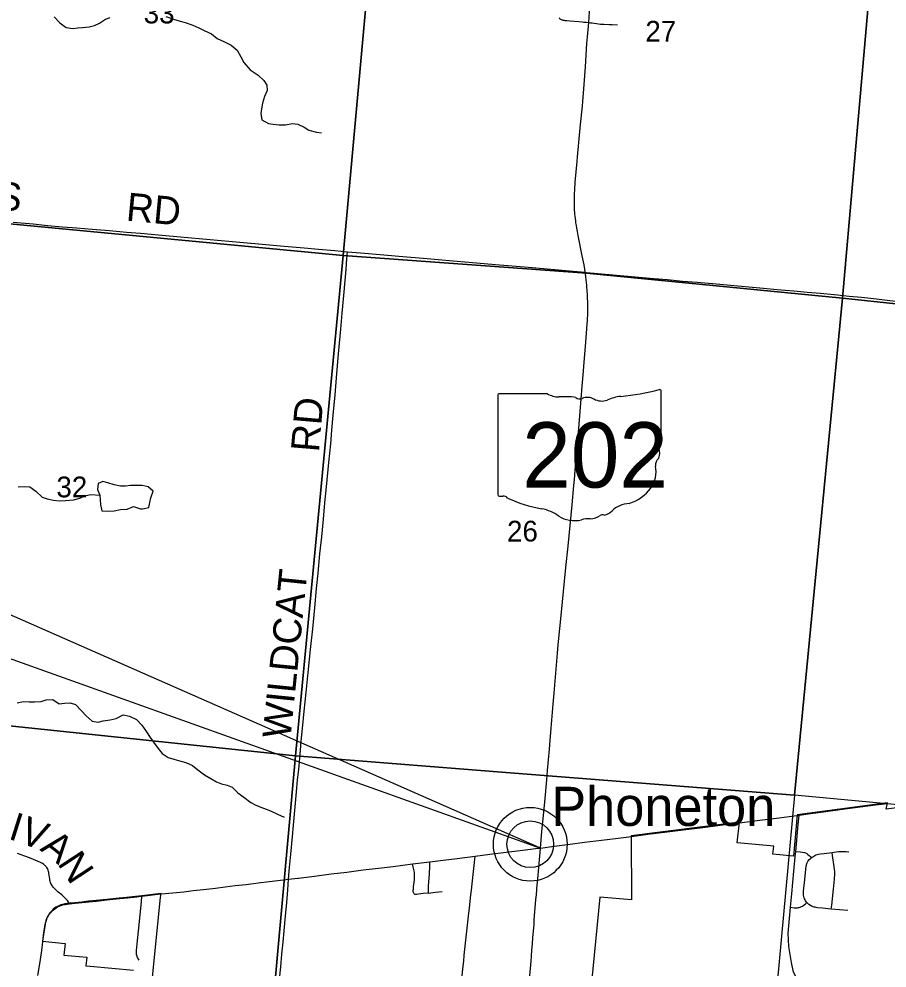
# Model space of a CAD drawing. Extents: x -38.1 to 35.9, y -2.7 to 28.5.
# Drawn here: x 10.521 to 12.272, y 15.8 to 17.716 of the extents above; entities that cross this region are included whole.
import ezdxf

# ---------------------------------------------------------------- set-up
doc = ezdxf.new("R2010")
doc.units = 0
for name, color, linetype in [('GM_X_City_Street', 7, 'Continuous'), ('GM_X_City_Street_Text', 7, 'Continuous'), ('GM_X_County_Road_Text', 7, 'Continuous'), ('GM_X_County_ROW', 7, 'Continuous'), ('GM_X_Interchange_Ramps', 7, 'Continuous'), ('GM_X_Major_River', 7, 'Continuous'), ('GM_X_Major_River_Text', 7, 'Continuous'), ('GM_X_Minor_Lake', 7, 'Continuous'), ('GM_X_Minor_River', 7, 'Continuous'), ('GM_X_Section', 7, 'Continuous'), ('GM_X_Section_Text', 7, 'Continuous'), ('GM_X_State_Location', 7, 'Continuous'), ('GM_X_Township', 7, 'Continuous'), ('GM_X_Township_Subdivision_Text', 7, 'Continuous'), ('GM_X_US_Route', 7, 'Continuous'), ('SC_Scratch10', 7, 'Continuous'), ('SH_Data', 7, 'Continuous')]:
    doc.layers.add(name, color=color, linetype=linetype)

msp = doc.modelspace()

# ---------------------------------------------------------------- linework, layer by layer
at = {"layer": 'GM_X_City_Street'}
for points in [[(12.1292, 15.6704), (12.132, 15.7051), (12.1322, 15.7158), (12.1298, 15.7265), (12.1267, 15.7376), (12.1232, 15.7458), (12.1172, 15.7524), (12.109, 15.7602), (12.0989, 15.7688), (12.0901, 15.7785), (12.0837, 15.7912), (12.0794, 15.8105), (12.0743, 15.8428), (12.0726, 15.8703), (12.0757, 15.8994), (12.0778, 15.9222), (12.0802, 15.9495), (12.0846, 15.9951), (12.0873, 16.0243), (12.0883, 16.0352), (12.0931, 16.0896), (12.0949, 16.1084)], [(12.0883, 16.0352), (12.0974, 16.0344), (12.1021, 16.0338), (12.1057, 16.033), (12.1081, 16.0321), (12.1104, 16.0308), (12.1129, 16.029), (12.1153, 16.027), (12.1173, 16.0249), (12.1195, 16.0221), (12.1224, 16.0243), (12.1248, 16.0258), (12.1269, 16.027), (12.129, 16.028), (12.1313, 16.0287), (12.1339, 16.0293), (12.1379, 16.0301), (12.1453, 16.0311), (12.1619, 16.0331), (12.1748, 16.0346), (12.1802, 16.0351), (12.1848, 16.0352), (12.1901, 16.0349), (12.1951, 16.0344)], [(12.1934, 15.9158), (12.1599, 15.9188), (12.1425, 15.9203), (12.1321, 15.9215), (12.1296, 15.9218), (12.1272, 15.9223), (12.1254, 15.9227), (12.1236, 15.9233), (12.1216, 15.924), (12.1193, 15.925), (12.1177, 15.9259), (12.1147, 15.928), (12.1126, 15.9298), (12.1108, 15.9318), (12.1094, 15.9336), (12.1082, 15.9356), (12.1071, 15.9376), (12.1062, 15.9395), (12.1054, 15.9415), (12.1047, 15.9439), (12.1042, 15.9466), (12.1041, 15.9494), (12.104, 15.9518), (12.1041, 15.9546), (12.1066, 15.9782), (12.108, 15.9926), (12.1092, 16.0052), (12.1097, 16.0076), (12.1106, 16.011), (12.1118, 16.0137), (12.1133, 16.0159), (12.1149, 16.0179), (12.1172, 16.0202), (12.1195, 16.0221)], [(12.1599, 15.9188), (12.1608, 15.9268), (12.1642, 15.9588), (12.1662, 15.9791), (12.1669, 15.9897), (12.167, 15.9928), (12.1669, 15.9953), (12.1667, 15.998), (12.166, 16.0037), (12.1627, 16.0271), (12.1619, 16.0331)], [(10.763, 15.8153), (10.7598, 15.8207), (10.7589, 15.8228), (10.7583, 15.8248), (10.7579, 15.8271), (10.7577, 15.8312), (10.7578, 15.8351), (10.759, 15.8488), (10.7617, 15.8742), (10.765, 15.907), (10.7678, 15.9331), (10.7687, 15.9447)], [(12.0778, 15.9222), (12.0848, 15.9215), (12.0886, 15.9213), (12.0919, 15.9214), (12.0935, 15.9216), (12.0951, 15.9219), (12.0968, 15.9223), (12.0984, 15.9229), (12.1, 15.9236), (12.1016, 15.9246), (12.105, 15.927), (12.1078, 15.9292), (12.1108, 15.9318)]]:
    msp.add_lwpolyline(points, dxfattribs=at)
at = {"layer": 'GM_X_City_Street_Text'}
for points in [[(10.5085, 17.3054), (10.5492, 17.3018), (10.5782, 17.2989), (10.6083, 17.2963), (10.6375, 17.2938), (10.6684, 17.2914), (10.7035, 17.2884), (10.7375, 17.2854), (10.766, 17.283), (10.809, 17.2792), (10.8464, 17.2758), (10.9665, 17.2651), (11.0184, 17.2603), (11.0558, 17.257), (11.0962, 17.2536), (11.125, 17.2509), (11.1577, 17.2481), (11.1835, 17.2458)], [(11.1835, 17.2458), (11.2097, 17.2436), (11.2496, 17.2401), (11.287, 17.2368), (11.3445, 17.2318), (11.3668, 17.2299), (11.3965, 17.2275), (11.4281, 17.2249), (11.482, 17.2201), (11.5073, 17.2179), (11.5408, 17.215), (11.6095, 17.2089), (11.6392, 17.2062), (11.6635, 17.2042)], [(11.6635, 17.2042), (11.6658, 17.204), (11.719, 17.1992), (11.7718, 17.1946), (11.8019, 17.1918), (11.8297, 17.1894), (11.8594, 17.1866), (11.8891, 17.184), (11.9275, 17.1807), (11.9789, 17.1762), (12.0228, 17.1722), (12.0507, 17.1697), (12.0841, 17.1667), (12.1113, 17.1642), (12.1379, 17.1618), (12.1725, 17.1585), (12.196, 17.1562), (12.2207, 17.1537), (12.251, 17.1504), (12.2778, 17.1474), (12.3036, 17.1446), (12.3242, 17.1423)], [(10.6222, 15.9293), (10.6211, 15.9314), (10.6198, 15.9337), (10.6181, 15.9361), (10.616, 15.9385), (10.6144, 15.9402), (10.6109, 15.9434), (10.6068, 15.9472), (10.5997, 15.9531), (10.5921, 15.9602), (10.5896, 15.963), (10.5884, 15.9646), (10.5872, 15.9663), (10.5859, 15.9683), (10.585, 15.9705), (10.5842, 15.9725), (10.5835, 15.9748), (10.5829, 15.9771), (10.5825, 15.9794), (10.5808, 15.9904), (10.5805, 15.9927), (10.58, 15.9948), (10.5794, 15.9971), (10.5787, 15.999), (10.5778, 16.0008), (10.5768, 16.0024), (10.5759, 16.0036), (10.5748, 16.0049), (10.574, 16.0058), (10.5729, 16.0067), (10.5716, 16.0079), (10.5699, 16.0091), (10.5679, 16.0104), (10.5656, 16.0117), (10.5628, 16.0131), (10.5594, 16.0148), (10.5501, 16.0186), (10.5415, 16.0221), (10.5322, 16.0256), (10.5177, 16.031)]]:
    msp.add_lwpolyline(points, dxfattribs=at)
at = {"layer": 'GM_X_County_ROW'}
msp.add_line((11.5524, 16.0495), (11.5524, 16.0495), dxfattribs=at)
at = {"layer": 'GM_X_Interchange_Ramps'}
for points in [[(11.5856, 16.1795), (11.5872, 16.1983), (11.5912, 16.2416), (11.5925, 16.259), (11.5945, 16.2837), (11.5989, 16.3326), (11.6006, 16.3543), (11.6075, 16.4353), (11.6089, 16.452), (11.6154, 16.5181), (11.6218, 16.5806), (11.6245, 16.6084), (11.6289, 16.651), (11.6371, 16.7345), (11.6406, 16.7735), (11.6416, 16.786), (11.6445, 16.8225), (11.649, 16.8748), (11.6502, 16.8888), (11.6573, 16.9741), (11.66, 17.0045), (11.6608, 17.015), (11.6639, 17.0546), (11.6674, 17.0992), (11.6678, 17.1067), (11.6684, 17.122), (11.6686, 17.1282), (11.6686, 17.1344), (11.6686, 17.1395), (11.668, 17.1572), (11.6674, 17.1682), (11.6669, 17.1737), (11.6665, 17.1792), (11.6662, 17.1828), (11.6654, 17.1899), (11.6648, 17.195), (11.664, 17.2012), (11.6635, 17.2042), (11.6626, 17.2102), (11.661, 17.2195), (11.6573, 17.2377), (11.6493, 17.2782), (11.6478, 17.2863), (11.6465, 17.2935), (11.6456, 17.2986), (11.6447, 17.3042), (11.6442, 17.3077), (11.6435, 17.3135), (11.6426, 17.3213), (11.642, 17.3328), (11.6415, 17.3466), (11.6415, 17.3531), (11.6418, 17.3626), (11.6422, 17.3707), (11.6432, 17.3864), (11.6468, 17.4278), (11.6477, 17.4376), (11.654, 17.5023), (11.6576, 17.5394), (11.6584, 17.5491), (11.6612, 17.5832), (11.6638, 17.6191), (11.6669, 17.6664), (11.6679, 17.6794), (11.6704, 17.7083), (11.6727, 17.7407)], [(11.5733, 16.0419), (11.576, 16.0752), (11.579, 16.1073), (11.5823, 16.142), (11.5856, 16.1795)], [(11.5658, 15.9605), (11.5674, 15.9799), (11.5697, 16.0028), (11.5732, 16.0411), (11.5733, 16.0419)], [(11.5379, 15.6318), (11.5386, 15.6393), (11.5413, 15.6702), (11.5426, 15.6831), (11.5462, 15.7227), (11.5501, 15.7685), (11.5503, 15.772), (11.5513, 15.7846), (11.554, 15.8136), (11.5557, 15.8353), (11.5567, 15.8489), (11.5577, 15.8606), (11.56, 15.8885), (11.5606, 15.8976), (11.5618, 15.9131), (11.5639, 15.9378), (11.5647, 15.9471), (11.5656, 15.9576), (11.5658, 15.9605)]]:
    msp.add_lwpolyline(points, dxfattribs=at)
at = {"layer": 'GM_X_Major_River'}
for points in [[(12.0949, 16.1084), (12.1179, 16.1115), (12.1444, 16.115), (12.1826, 16.1202), (12.2179, 16.1248), (12.2491, 16.1289), (12.2735, 16.132)], [(11.9748, 16.0928), (12.0159, 16.098), (12.0545, 16.1031), (12.0949, 16.1084)], [(11.7565, 16.0655), (11.7895, 16.0697), (11.8284, 16.0746), (11.8613, 16.0787), (11.9007, 16.0836), (11.9412, 16.0889), (11.9748, 16.0928)], [(11.0845, 15.9813), (11.1168, 15.9853), (11.1503, 15.9896), (11.1825, 15.9935), (11.2153, 15.9976), (11.2464, 16.0015), (11.2754, 16.0048), (11.3149, 16.0097), (11.3498, 16.0141), (11.3765, 16.0174), (11.405, 16.021), (11.4409, 16.0253), (11.4709, 16.0295), (11.5036, 16.0336), (11.5374, 16.0375), (11.5685, 16.0413), (11.5733, 16.0419), (11.6009, 16.0456), (11.633, 16.0497), (11.662, 16.0535), (11.6965, 16.0579), (11.7296, 16.0621), (11.7565, 16.0655)], [(11.0546, 15.9778), (11.0646, 15.9791), (11.0836, 15.9812), (11.0845, 15.9813)], [(10.8078, 15.9492), (10.8311, 15.9515), (10.8531, 15.9538), (10.8721, 15.9559), (10.8932, 15.9582), (10.9172, 15.961), (10.9369, 15.9635), (10.9567, 15.966), (10.9788, 15.9685), (11.0029, 15.9715), (11.0257, 15.9743), (11.0546, 15.9778)], [(10.5686, 15.8528), (10.5702, 15.866), (10.5723, 15.8793), (10.5736, 15.8867), (10.5743, 15.8906), (10.5753, 15.8943), (10.5765, 15.898), (10.5777, 15.9011), (10.5791, 15.9039), (10.5809, 15.907), (10.5829, 15.9098), (10.5852, 15.9124), (10.5876, 15.915), (10.59, 15.9173), (10.5927, 15.9194), (10.5955, 15.9213), (10.5985, 15.9229), (10.6016, 15.9245), (10.6051, 15.9258), (10.609, 15.927), (10.6137, 15.928), (10.6178, 15.9287), (10.6222, 15.9293), (10.6339, 15.9305), (10.6477, 15.9318), (10.6612, 15.9332), (10.677, 15.9348), (10.698, 15.9371), (10.7233, 15.9398), (10.7393, 15.9416), (10.7585, 15.9437), (10.7687, 15.9447), (10.7799, 15.9459), (10.7951, 15.9478), (10.8078, 15.9492)], [(10.5586, 15.7845), (10.561, 15.7999), (10.5637, 15.8172), (10.5663, 15.8352), (10.5686, 15.8528)]]:
    msp.add_lwpolyline(points, dxfattribs=at)
at = {"layer": 'GM_X_Major_River_Text'}
for points in [[(11.6109, 17.7178), (11.6113, 17.7172), (11.6117, 17.7167), (11.6123, 17.7161), (11.6133, 17.7154), (11.6146, 17.7147), (11.6159, 17.7141), (11.6175, 17.7136), (11.6187, 17.7133), (11.621, 17.7129), (11.622, 17.7127), (11.6243, 17.7125), (11.6263, 17.7122), (11.6322, 17.7117), (11.6503, 17.7102), (11.6569, 17.7097), (11.6606, 17.7094), (11.6653, 17.7089), (11.6704, 17.7083)], [(11.6704, 17.7083), (11.6737, 17.708), (11.6774, 17.7075), (11.6902, 17.7057), (11.6943, 17.7053), (11.7006, 17.7048), (11.7115, 17.7044), (11.718, 17.7043), (11.7288, 17.7041)], [(11.0646, 15.9791), (11.0664, 16.0023), (11.0692, 16.0295), (11.0723, 16.0654), (11.0744, 16.0883), (11.0778, 16.1253), (11.0806, 16.1556), (11.0829, 16.1796), (11.085, 16.2007), (11.0884, 16.2396), (11.0902, 16.2575), (11.0925, 16.2829), (11.0962, 16.318), (11.1001, 16.3557), (11.1043, 16.3965), (11.1091, 16.4429), (11.1133, 16.4843), (11.1175, 16.5269), (11.1213, 16.5658), (11.1243, 16.5968), (11.1279, 16.6356), (11.1315, 16.6703), (11.1353, 16.7061), (11.1381, 16.739), (11.1411, 16.7708), (11.1461, 16.8203), (11.1496, 16.8581), (11.1521, 16.8853), (11.1547, 16.9156), (11.1584, 16.9571), (11.1615, 16.9911), (11.165, 17.0325), (11.1674, 17.0613), (11.1698, 17.0891), (11.1728, 17.1219), (11.1761, 17.1576), (11.179, 17.1874), (11.181, 17.2099), (11.1825, 17.2322), (11.1835, 17.2458)], [(11.4149, 15.784), (11.4163, 15.7978), (11.418, 15.8137), (11.4192, 15.8256), (11.4205, 15.8375), (11.4279, 15.9044), (11.4297, 15.9211), (11.4326, 15.9477), (11.4335, 15.9569), (11.4349, 15.9699), (11.4409, 16.0253)], [(11.3471, 15.9511), (11.3363, 15.9498), (11.3268, 15.9487), (11.3233, 15.9483), (11.3222, 15.9482), (11.3214, 15.9483), (11.3207, 15.9483), (11.32, 15.9484), (11.3188, 15.9489), (11.3178, 15.9496), (11.3171, 15.9506), (11.3166, 15.9518), (11.3165, 15.9526), (11.3164, 15.9537), (11.3164, 15.9551), (11.3164, 15.9568), (11.3166, 15.9587), (11.317, 15.9634), (11.3176, 15.9685), (11.3186, 15.9774), (11.3189, 15.9824), (11.319, 15.9868), (11.3185, 15.9918), (11.3178, 15.9959), (11.3162, 16.0038), (11.3149, 16.0097)], [(11.3471, 15.9511), (11.347, 15.9582), (11.3473, 15.966), (11.3477, 15.9727), (11.349, 15.9896), (11.3497, 16.0053), (11.3498, 16.0141)], [(11.0419, 15.7237), (11.0446, 15.7524), (11.0465, 15.7775), (11.0487, 15.8019), (11.0513, 15.8274), (11.0525, 15.8398), (11.0534, 15.8516), (11.0556, 15.8746), (11.0587, 15.9053), (11.0603, 15.9246), (11.0617, 15.9402), (11.0632, 15.9573), (11.0646, 15.9791)], [(11.3471, 15.9511), (11.3614, 15.9527), (11.3744, 15.9542)]]:
    msp.add_lwpolyline(points, dxfattribs=at)
at = {"layer": 'GM_X_Section'}
for points in [[(10.5918, 17.7197), (10.6027, 17.7078), (10.6154, 17.6985), (10.6294, 17.6961), (10.6393, 17.6975), (10.6488, 17.6985), (10.6621, 17.6999), (10.6731, 17.7024), (10.6827, 17.7072), (10.6949, 17.7154), (10.7044, 17.7183)], [(10.8171, 17.7204), (10.8325, 17.7153), (10.8458, 17.7113), (10.856, 17.7085), (10.8715, 17.7034), (10.8835, 17.698), (10.8941, 17.6921), (10.9088, 17.6855), (10.9208, 17.6759), (10.9351, 17.6692), (10.9487, 17.663), (10.9611, 17.6526), (10.9685, 17.6392), (10.9745, 17.6274), (10.9872, 17.6132), (11.003, 17.602), (11.0146, 17.5916), (11.0209, 17.5817), (11.0216, 17.5714), (11.0161, 17.5593), (11.0122, 17.5457), (11.0098, 17.5343), (11.0089, 17.5249), (11.0106, 17.5123), (11.0238, 17.5049), (11.0336, 17.5029), (11.0454, 17.502), (11.0587, 17.5022), (11.0723, 17.5044), (11.083, 17.5035), (11.0958, 17.4972), (11.1056, 17.4914), (11.1211, 17.4871), (11.1313, 17.4858)], [(10.5191, 16.7713), (10.5316, 16.7719), (10.5426, 16.771), (10.5546, 16.7625), (10.5674, 16.7502), (10.5772, 16.7467), (10.5905, 16.7442), (10.6018, 16.743), (10.6147, 16.7436), (10.6303, 16.7449), (10.6432, 16.7482), (10.6535, 16.7526), (10.6653, 16.7555), (10.6835, 16.7541)], [(10.517, 16.3349), (10.5299, 16.3378), (10.5409, 16.3369), (10.5515, 16.3368), (10.5656, 16.3377), (10.5755, 16.341), (10.5887, 16.342), (10.6019, 16.3328), (10.6125, 16.3345), (10.6235, 16.3352), (10.6349, 16.3316), (10.6469, 16.3186), (10.6562, 16.309), (10.6682, 16.2978), (10.6803, 16.2962), (10.6906, 16.2987), (10.7043, 16.3008), (10.7165, 16.3037), (10.731, 16.3107), (10.7438, 16.3079), (10.7574, 16.3013), (10.7686, 16.2898), (10.778, 16.2764), (10.7854, 16.2653), (10.7917, 16.2554), (10.8011, 16.2427), (10.8093, 16.2328), (10.8213, 16.2247), (10.8327, 16.2215), (10.847, 16.2175), (10.8572, 16.2144), (10.8704, 16.2085), (10.8813, 16.2), (10.8952, 16.1896), (10.9077, 16.1823), (10.919, 16.1753), (10.9292, 16.1714), (10.9405, 16.1686), (10.9507, 16.1647), (10.9619, 16.1535), (10.9744, 16.1443), (10.9886, 16.1339), (10.9984, 16.1284), (11.0139, 16.1222), (11.0283, 16.1171), (11.0422, 16.1105), (11.0554, 16.1039)]]:
    msp.add_lwpolyline(points, dxfattribs=at)
at = {"layer": 'GM_X_Section_Text'}
for p, q in [((11.5869, 16.9591), (11.4904, 16.9591)), ((11.8167, 16.8593), (11.8167, 16.964)), ((11.4871, 16.9556), (11.4871, 16.7555)), ((11.8167, 16.8594), (11.8167, 16.8593))]:
    msp.add_line(p, q, dxfattribs=at)
for centre, major_axis, start_param, end_param in [((11.4909, 16.956), (0.00382, 0), 1.712693, 3.28349), ((11.6099, 16.9823), (0.037, 0), 4.042523, 4.731795), ((11.6993, 17.2319), (0.3495, 0), 4.814394, 5.042369), ((11.8131, 16.9644), (0.00367, 0), 6.141152, 7.989035), ((11.6222, 16.8467), (0.133, 0), 1.404758, 1.657858), ((11.6524, 16.9571), (0.0107, 0), 3.836095, 5.185415), ((11.668, 16.9339), (0.0222, 0), 0.950623, 2.079405), ((11.6967, 16.9657), (0.0267, 0), 4.081561, 5.145723), ((11.7439, 16.8979), (0.0703, 0), 1.699011, 2.107814), ((11.8159, 16.8516), (0.00568, 0), 1.883978, 3.671073), ((11.7798, 16.8384), (0.0341, 0), 5.934695, 6.695948), ((11.8128, 16.8589), (0.00393, 0), 5.05454, 6.418171), ((11.8299, 16.8155), (0.0248, 0), 2.387724, 3.262537), ((11.7189, 16.8022), (0.0874, 0), 5.101752, 6.440018), ((11.4909, 16.755), (0.00385, 0), 3.00124, 4.508301), ((11.4915, 16.7755), (0.0294, 0), 4.665946, 4.897461), ((11.4975, 16.7439), (0.0106, 0), 0.519207, 1.627899), ((11.6314, 16.9237), (0.2524, 0), 4.195997, 4.488961), ((11.5561, 16.6656), (0.079, 0), 0.823519, 1.323587), ((11.7558, 16.6993), (0.0479, 0), 1.647645, 2.488434), ((11.6415, 16.7429), (0.0501, 0), 4.026481, 4.996735), ((11.6705, 16.6738), (0.0412, 0), 1.495662, 1.94098), ((11.6741, 16.728), (0.0267, 0), 4.691044, 5.507374), ((11.6983, 16.7086), (0.00752, 0), 1.147584, 2.315152), ((11.6951, 16.7361), (0.0282, 0), 4.937069, 5.64225)]:
    msp.add_ellipse(centre, major_axis=major_axis, ratio=0.8, start_param=start_param, end_param=end_param, dxfattribs=at)
at = {"layer": 'GM_X_State_Location'}
for radius in [0.0744, 0.0472]:
    msp.add_circle((11.5524, 16.0495), radius, dxfattribs=at)
at = {"layer": 'GM_X_US_Route'}
for points in [[(11.2671, 18.2524), (11.175, 17.2383), (10.1754, 17.3332), (10.2004, 17.5967), (10.2059, 17.6034), (10.2144, 17.6165), (10.2277, 17.6393), (10.239, 17.6539), (10.253, 17.6718), (10.2658, 17.6882), (10.2762, 17.7002), (10.2928, 17.7169)], [(10.0836, 16.332), (11.0788, 16.2278), (10.9892, 15.2394), (10.3866, 15.2973)], [(12.5609, 15.7367), (12.5712, 15.8516), (12.3147, 15.8755), (12.3481, 16.123), (12.3137, 16.1259), (12.271, 16.1201), (12.2731, 16.133), (12.0913, 16.1088), (12.0834, 16.0256), (12.0422, 16.0293), (12.0437, 16.0454), (11.9701, 16.0524), (11.9744, 16.0939), (11.7561, 16.0665), (11.7566, 15.9376), (11.6928, 15.943), (11.6675, 15.6807)], [(10.7865, 15.7477), (10.8061, 15.9422), (10.8074, 15.9502), (10.7683, 15.9456), (10.7247, 15.941), (10.7229, 15.9408), (10.6976, 15.9382), (10.6766, 15.9358), (10.6609, 15.9343), (10.6474, 15.9328), (10.6335, 15.9315), (10.6218, 15.9303), (10.6174, 15.9297), (10.6133, 15.929), (10.6086, 15.928), (10.6047, 15.9269), (10.6012, 15.9255), (10.5981, 15.924), (10.5951, 15.9223), (10.5923, 15.9204), (10.5897, 15.9183), (10.5872, 15.916), (10.5848, 15.9134), (10.5826, 15.9108), (10.5805, 15.908), (10.5787, 15.905), (10.5773, 15.9021), (10.5761, 15.899), (10.5749, 15.8954), (10.5739, 15.8916), (10.5732, 15.8877), (10.5719, 15.8803), (10.5699, 15.8671), (10.5682, 15.8538), (10.6138, 15.8495), (10.6108, 15.8259), (10.6577, 15.8218), (10.6555, 15.8044), (10.664, 15.8036), (10.7517, 15.7955)]]:
    msp.add_lwpolyline(points, dxfattribs=at)
for points in [[(11.2671, 18.2524), (12.2713, 18.1647), (12.1826, 17.1517), (11.6659, 17.2023), (11.175, 17.2383)], [(13.2752, 18.0746), (13.1908, 17.0449), (12.1826, 17.1517), (12.2713, 18.1647)], [(10.1754, 17.3332), (11.175, 17.2383), (11.0788, 16.2278), (10.0836, 16.332)], [(11.175, 17.2383), (11.6659, 17.2023), (12.1826, 17.1517), (12.0859, 16.1484), (11.4865, 16.196), (11.0788, 16.2278)], [(13.1908, 17.0449), (13.1005, 16.0538), (12.0859, 16.1484), (12.1826, 17.1517)], [(11.0788, 16.2278), (11.4865, 16.196), (12.0859, 16.1484), (11.9927, 15.1412), (10.9892, 15.2394)]]:
    msp.add_lwpolyline(points, close=True, dxfattribs=at)
at = {"layer": 'SC_Scratch10'}
for points in [[(10.77, 16.7265), (10.7825, 16.7294), (10.7846, 16.7393), (10.7866, 16.7491), (10.7913, 16.7623), (10.7815, 16.7712), (10.769, 16.7736), (10.7561, 16.7741), (10.7459, 16.7739), (10.7353, 16.7721), (10.7254, 16.7722), (10.7129, 16.775), (10.7001, 16.7794), (10.6899, 16.7818), (10.6803, 16.7781), (10.6791, 16.7659), (10.6835, 16.7541)], [(10.6835, 16.7541), (10.6851, 16.7351), (10.688, 16.7226), (10.6994, 16.7217), (10.7127, 16.7227), (10.7256, 16.7255), (10.7389, 16.7258), (10.7518, 16.7313), (10.7658, 16.7266), (10.77, 16.7265)]]:
    msp.add_lwpolyline(points, dxfattribs=at)
at = {"layer": 'SH_Data'}
msp.add_lwpolyline([(7.839, 17.3766), (11.5732, 16.0414), (7.839, 17.6847)], close=True, dxfattribs=at)

# ---------------------------------------------------------------- texts
at = {"layer": 'GM_X_County_Road_Text'}
for s in ['s', 'r']:
    msp.add_text(s, height=0.000189, dxfattribs=at).set_placement((11.6482, 16.8422))
msp.add_text('202', height=0.000189, rotation=0, dxfattribs=at).set_placement((11.5814, 16.8285))
at = {"layer": 'GM_X_Minor_Lake'}
for s, rotation, p in [('RD', 85.1564, (11.1258, 16.84)), ('WILDCAT', 84.2002, (11.0683, 16.2612))]:
    msp.add_text(s, height=0.05682, rotation=rotation, dxfattribs=at).set_placement(p)
at = {"layer": 'GM_X_Minor_River'}
for s, p in [('33', (10.7722, 17.7066)), ('27', (11.7847, 17.6699)), ('32', (10.596, 16.7499)), ('26', (11.5055, 16.6607))]:
    msp.add_text(s, height=0.04186, rotation=0, dxfattribs=at).set_placement(p)
at = {"layer": 'GM_X_Section_Text'}
msp.add_text('202', height=0.13184, dxfattribs=at).set_placement((11.5361, 16.7696))
at = {"layer": 'GM_X_Township'}
for s, height, rotation, p in [('ROSS', 0.05682, 354.7755, (10.3093, 17.3463)), ('RD', 0.05682, 354.6263, (10.7353, 17.3087)), ('I', 0.0568, 342.4574, (10.497, 16.0609)), ('V', 0.0568, 338.9873, (10.5184, 16.0542)), ('A', 0.0568, 321.4142, (10.5611, 16.0386)), ('N', 0.0568, 303.294, (10.597, 16.0109))]:
    msp.add_text(s, height=height, rotation=rotation, dxfattribs=at).set_placement(p)
at = {"layer": 'GM_X_Township_Subdivision_Text'}
msp.add_text('Phoneton', height=0.07898, rotation=0, dxfattribs=at).set_placement((11.5947, 16.0865))

doc.saveas('drawing.dxf')
